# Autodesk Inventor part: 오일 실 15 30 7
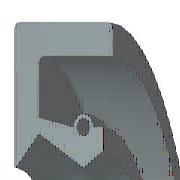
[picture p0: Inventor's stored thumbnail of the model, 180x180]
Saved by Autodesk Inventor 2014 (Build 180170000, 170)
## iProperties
IsCustomPart: 1
Created: 2012-02
Part Number: 오일 실 15 30 7
Material: 고무
Description: 오일-실
Document SubType Name: Modeling
Standard: KS B 2804
Designer: mduedu
Standards Organization: KS
Language: ko-KR
Size Designation: D - 15 30 7
Categories: <MemberInstance><Categories><Category DisplayName="샤프트 부품" InternalName="7f7aeb1f-a693-4053-b835-cee3144e0d98" Mnemonic="SHFT"><Category DisplayName="실링" Intern
Density: 0.93 g/cm^3
Appearance: Rubber - Black - Version 1.1
Author: mduedu
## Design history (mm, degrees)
revolve "본체" stored, may be unused: angle "d17" = 90 deg
revolve "스프링1" stored, may be unused: angle "d18" = 90 deg
body "Solid1"
sketch "스케치1"
  geometry: L1 (0, 15)-(7, 15); L2 (7, 13.25)-(1.75, 13.25); L3 (1.75, 9.25)-(4.9, 7.5); L4 (4.9, 7.5)-(0, 7.5); L5 (0, 0)-(9.586, 0) reference; L6 (4.9, 7.5)-(6.3, 8.375); L7 (0, 18)-(0, -3) reference; L8 (-1.941, 0)-(11.507, 0) reference; L9 (4.2, 9.6)-(1.75, 10.09); L10 (1.75, 10.09)-(1.75, 13.25); L11 (0, 15)-(0, 7.588); L12 (4.9, 7.5)-(0, 7.5); L13 (1.75, 9.25)-(0.152, 7.528); L14 (7, 15)-(7, 13.25); L15 (5.6, 9.6)-(6.3, 9.6); L16 (6.3, 9.6)-(6.3, 8.375); C1 r 0.455 at (4.9, 9.6); A1 r 0.7 centre (4.9, 9.6) between (5.6, 9.6) and (4.2, 9.6); A2 r 0.088 centre (0.088, 7.588) between (0, 7.588) and (0.152, 7.528); 1 further point
  constraints: 28 end point, 5 horizontal alignment, 5 point on line, 4 point on circle, 4 vertical alignment, 3 centre point, 3 tangent, 2 collinear, 2 horizontal, 2 perpendicular, 1 coincident, 1 parallel
  dimensions: "d0" = 30 diameter of L1 L5 (= SD2); "d1" = 1.75 distance of L1.end L2.start (= SD); "d2" = 0.91 diameter of C1 (= SPDI); "d3" = 1.4 diameter of A1 (= SPDA); "d4" = 15 diameter of L3.end L5 (= NND); "d5" = 18.5 diameter of L3.start L5 (= TKDM); "d7" = 20.18 diameter of L9.end L5 (= TKDM + 0.24 x SWDT); "d8" = 1.75 distance between parallel lines of L11 L10 (= SD); "d9" = 4.9 distance from line of L11 C1.centre (= SPDST); "d10" = 19.2 diameter of C1.centre L5 (= HLDM); "d11" = 0.0875 radius of A2 (= 0.25 x LAB); "d12" = 6.3 distance between parallel lines of L11 L16 (= SDI); "d13" = 16.75 diameter of L6.end L5 (= ABDM); "d14" = 7 distance from line of L11 L1.end (= SWDT)
fillet "모깎기1" dims "d6" = 0.3 (= RR)
other parameters: "SD2" = 30 [user parameter; used in 1 equation term], "SWDT" = 7 [user parameter; used in 2 equation terms], "RR" = 0.3 [user parameter; used in 1 equation term], "SD" = 1.75 [user parameter; used in 2 equation terms], "NND" = 15 [user parameter; used in 1 equation term], "SPDA" = 1.4 [user parameter; used in 1 equation term], "SPDI" = 0.91 [user parameter; used in 1 equation term], "TKDM" = 18.5 [user parameter; used in 2 equation terms], "HLDM" = 19.2 [user parameter; used in 1 equation term], "ABDM" = 16.75 [user parameter; used in 1 equation term], "SDI" = 6.3 [user parameter; used in 1 equation term], "SPDST" = 4.9 [user parameter; used in 1 equation term], "LAB" = 0.35 [user parameter; used in 1 equation term], "d15" = 0, "d16" = 0, "d19" = 0
